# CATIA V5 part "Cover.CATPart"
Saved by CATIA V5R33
Part number: Cover
Bounding box of the stored display mesh (mm): x -49.812 to 35, y -44.222 to 44.222, z 0 to 30.5
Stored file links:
  D:\PROJECTS\Project 2023\CATIA V5 6R 2023\Resources\Tutorial Files\c12_catia_v5_6r2023_tut\c12Tut1\Cover.CATPart
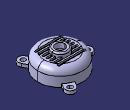
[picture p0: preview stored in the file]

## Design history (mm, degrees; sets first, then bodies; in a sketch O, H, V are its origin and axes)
Body1 (main body)
  Sketch1 on xy-plane, origin (0, 0, 0), H (1, 0, 0), V (0, 1, 0)
    circle A1 centre (0, 0) radius 35
    radius A1 = 35
  Pad1: profile Sketch1, direction (0, 0, 1), length 25
  Fillet1: radius 10, on 1 edge
  Shell1: ExtOffset 0, Face face, IntOffset 2.5
  Sketch2 on face of Pad1, origin (0, 0, 25), H (1, 0, 0), V (0, 1, 0)
    construction line L1 (-20, 0) -> (20, 0)
    point P1 (-20, 0)
    line L2 (-20, 1.75) -> (20, 1.75)
    line L3 (20, -1.75) -> (-20, -1.75)
    arc A1 centre (20, 0) radius 1.75 from (20, 1.75) to (20, -1.75) cw
    arc A2 centre (-20, 0) radius 1.75 from (-20, -1.75) to (-20, 1.75) cw
    length L1 = 40
    radius A1 = 1.75
    distance P1 V = 20
    coincidence: P1 H
    horizontal: L1 H
    tangency: A1 L2, A2 L2, A1 L3, A2 L3
    parallelism: L1 L2
  Pocket1: profile Sketch2, direction (0, 0, -1), length 12.7
  RectPattern1: of Pocket1, direction 1 instances 1, spacing 6, along xy-plane, direction 2 instances 7, spacing 6, along xy-plane, Nv 4
  Sketch3 on face of Shell1, origin (0, 0, 22.5), H (1, 0, 0), V (0, -1, 0)
    circle A1 centre (0, 0) radius 12.5
    radius A1 = 12.5
  Pad2: profile Sketch3, direction (0, 0, 1), length 8
  Fillet2: radius 2, on 1 edge
  Sketch4 on face of Pad2, origin (0, 0, 30.5), H (1, 0, 0), V (0, 1, 0)
    circle A1 centre (0, 0) radius 7.5
    radius A1 = 7.5
  Pocket2: profile Sketch4, direction (0, 0, -1), through (limit type 6)
  Sketch5 on xy-plane, origin (0, 0, 0), H (1, 0, 0), V (0, 1, 0)
    projected arc E1 centre (0, 0) radius 35 from (-34.187, 7.5) to (-34.187, -7.5) ccw from edge of RectPattern1
    line L1 (-34.187, 7.5) -> (-42.5, 7.5)
    line L2 (-34.187, -7.5) -> (-42.5, -7.5)
    arc A1 centre (-42.5, 0) radius 7.5 from (-42.5, -7.5) to (-42.5, 7.5) cw
    point P5 (-42.5, 0)
    point P6 (-50, 0)
    circle A2 centre (-42.5, 0) radius 3.75
    radius A1 = 7.5
    distance V P5 = 42.5
    radius A2 = 3.75
    horizontal: L1 H, L2 H
    coincidence: A1 P6, P6 H, P5 H
    tangency: A1 L2, L1 A1
  Pad3: profile Sketch5, direction (0, 0, 1), length 5
  CircPattern1: of Pad3, instances 3, angular step 120, axis from xy-plane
